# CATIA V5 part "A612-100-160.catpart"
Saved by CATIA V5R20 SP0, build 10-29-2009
Part number: A612-100-160
Source: Unknown
Property "A": "30.000"
Property "ARTICLENO": "A612-100-160"
Property "B": "40.000"
Property "BOMINFO": "A612-100-160"
Property "CODE": "A612-100-160"
Property "D": "17.500"
Property "FORM": "A"
Property "L": "160.000"
Property "L1": "45.000"
Property "L2": "70.000"
Property "L3": "0.000"
Property "LINA": "A612-100-160"
Property "NB": "A612-100-160"
Property "NBSYN": "$CODE."
Property "NN": "A612"
Property "NT": "CDI 3357 E-Type Wear Plates, steel and self-lubricating"
Property "SUPPLIER": "CF"
Property "T": "25.000"
Property "W": "100.000"
Bounding box of the stored display mesh (mm): x 0 to 25, y 0 to 160, z 0 to 100
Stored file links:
  C:\Users\Utente\Desktop\3D files A612\A612-100-160.catpart
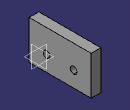
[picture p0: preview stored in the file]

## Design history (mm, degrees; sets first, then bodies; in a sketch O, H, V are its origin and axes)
Body1 "Geometry.1" (main body)
  Solid1 "A612-100-160.catpart": solid without history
